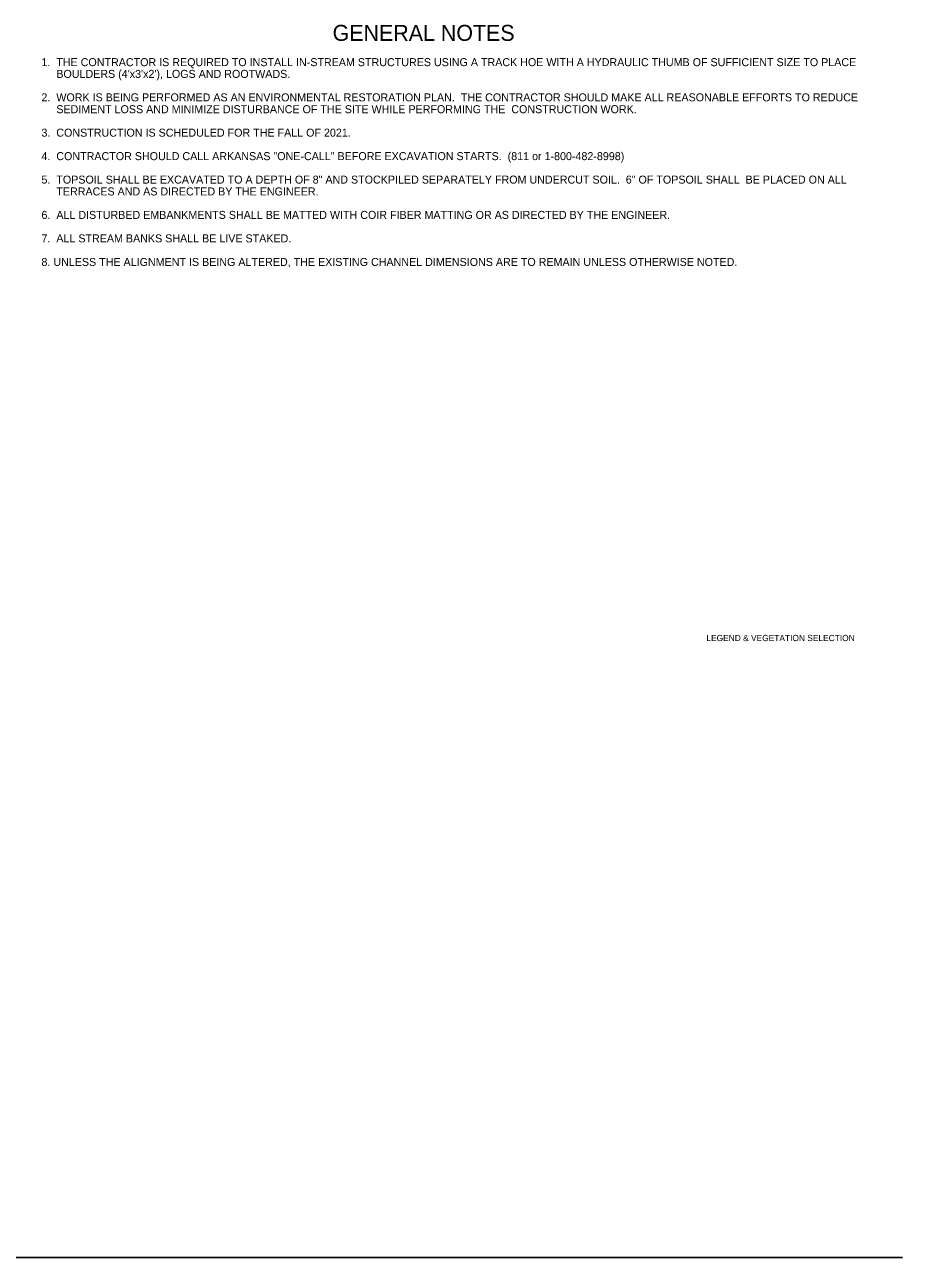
# Model space of a CAD drawing. Extents: x 1577194 to 26153757, y 723342 to 3772486.
# Drawn here: x 1577967 to 1578789, y 724102 to 725258 of the extents above; entities that cross this region are included whole.
import ezdxf

# ---------------------------------------------------------------- set-up
doc = ezdxf.new("R2010")
doc.units = 0
for name, color, linetype in [('L-CL', 7, 'Continuous'), ('Old_Level_1', 7, 'Continuous'), ('Old_Level_44', 7, 'Continuous'), ('R_Border', 7, 'Continuous')]:
    doc.layers.add(name, color=color, linetype=linetype)

msp = doc.modelspace()

# ---------------------------------------------------------------- linework, layer by layer
at = {"layer": 'L-CL'}
msp.add_line((1577194.1, 724102.1), (1578789.5, 724102.1), dxfattribs=at)

# ---------------------------------------------------------------- texts
at = {"layer": 'Old_Level_1'}
for s, p in [('1.  THE CONTRACTOR IS REQUIRED TO INSTALL IN-STREAM STRUCTURES USING A TRACK HOE WITH A HYDRAULIC THUMB OF SUFFICIENT SIZE TO PLACE', (1577982.9, 725218.8)), ("     BOULDERS (4'x3'x2'), LOGS AND ROOTWADS.", (1577982.9, 725207.8)), ('2.  WORK IS BEING PERFORMED AS AN ENVIRONMENTAL RESTORATION PLAN.  THE CONTRACTOR SHOULD MAKE ALL REASONABLE EFFORTS TO REDUCE', (1577982.9, 725185.8)), ('     SEDIMENT LOSS AND MINIMIZE DISTURBANCE OF THE SITE WHILE PERFORMING THE  CONSTRUCTION WORK.', (1577982.9, 725174.7)), ('3.  CONSTRUCTION IS SCHEDULED FOR THE FALL OF 2021.', (1577982.9, 725152.7)), ('4.  CONTRACTOR SHOULD CALL ARKANSAS "ONE-CALL" BEFORE EXCAVATION STARTS.  (811 or 1-800-482-8998)', (1577982.9, 725130.7)), ('5.  TOPSOIL SHALL BE EXCAVATED TO A DEPTH OF 8" AND STOCKPILED SEPARATELY FROM UNDERCUT SOIL.  6" OF TOPSOIL SHALL  BE PLACED ON ALL', (1577982.9, 725108.7)), ('     TERRACES AND AS DIRECTED BY THE ENGINEER.', (1577982.9, 725097.6)), ('6.  ALL DISTURBED EMBANKMENTS SHALL BE MATTED WITH COIR FIBER MATTING OR AS DIRECTED BY THE ENGINEER.', (1577982.9, 725075.6)), ('7.  ALL STREAM BANKS SHALL BE LIVE STAKED.', (1577982.9, 725053.6)), ('8. UNLESS THE ALIGNMENT IS BEING ALTERED, THE EXISTING CHANNEL DIMENSIONS ARE TO REMAIN UNLESS OTHERWISE NOTED.', (1577982.9, 725031.5))]:
    msp.add_text(s, height=7.5, dxfattribs=at).set_placement(p)
at = {"layer": 'Old_Level_44'}
msp.add_text('GENERAL NOTES', height=15, dxfattribs=at).set_placement((1578255.7, 725242.5))
at = {"layer": 'R_Border'}
msp.add_text('LEGEND & VEGETATION SELECTION', height=5.862, dxfattribs=at).set_placement((1578605.9, 724679.8))

doc.saveas('drawing.dxf')
